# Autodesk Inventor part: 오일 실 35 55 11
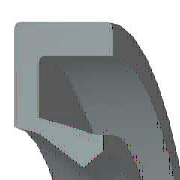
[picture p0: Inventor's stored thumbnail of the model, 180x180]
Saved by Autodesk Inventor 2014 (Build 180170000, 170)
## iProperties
IsCustomPart: 1
Created: 2012-02
Part Number: 오일 실 35 55 11
Material: 고무
Description: 오일 실 - 비스프링, 조립 GA
Document SubType Name: Modeling
Standard: JIS B 2402
Designer: mdu-01
Standards Organization: JIS
Language: ko-KR
Size Designation: 35 55 11 A
Categories: <MemberInstance><Categories><Category DisplayName="샤프트 부품" InternalName="7f7aeb1f-a693-4053-b835-cee3144e0d98" Mnemonic="SHFT"><Category DisplayName="실링" Intern
Density: 0.93 g/cm^3
Appearance: Rubber-Black
Mass: 8.95413 g
Surface Area: 69.7587 cm^2
Volume: 9.6281 cm^3
Author: mdu-01
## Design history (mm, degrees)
body "Solid1"
revolve "회전1" stored, may be unused: angle "d27" = 360 deg
fillet "모깎기1" dims "d28" = 0.55 (= 0.05 x b)
sketch "스케치2"
  geometry: L1 (20.786, -8.25)-(21.786, -11); L2 (19.452, -7.563)-(20.786, -8.25); L3 (17.5, -3.025)-(19.452, -7.563); L4 (19.038, -1.65)-(17.5, -3.025); L5 (23.5, -9.625)-(19.038, -1.65); L6 (23.5, -0.55)-(23.5, -9.625); L7 (25.5, -0.55)-(23.5, -0.55); L8 (25.5, 0)-(25.5, -0.55); L9 (27.5, 0)-(25.5, 0); L10 (27.5, -11)-(27.5, 0); L11 (21.786, -11)-(27.5, -11); L12 (0, -9.6)-(0, 1.6) reference; L13 (28, 0)-(14, 0) reference
  constraints: 22 end point, 3 horizontal, 3 vertical
  dimensions: "d2" = 11 distance of L10.start L9.start (= b); "d4" = 2 distance of L9.start L8.start (= 0.1 x dd - 0.1 x Diam); "d6" = 0.55 distance of L8.start L7.start (= 0.05 x b); "d8" = 1.53846 horizontal distance of L4.start L3.start (= 0.0769231 x dd - 0.0769231 x Diam); "d10" = 1.375 vertical distance of L5.start L10.start (= 0.125 x b); "d12" = 2 distance of L7.start L6.start (= 0.1 x dd - 0.1 x Diam); "d14" = 1.1 vertical distance of L4.start L6.start (= 0.1 x b); "d16" = 5.71429 distance of L1.end L10.start (= 0.285714 x dd - 0.285714 x Diam); "d18" = 1 horizontal distance of L1.start L1.end (= 0.05 x dd - 0.05 x Diam); "d20" = 1.375 vertical distance of L4.start L3.start (= 0.125 x b); "d22" = 2.75 vertical distance of L1.start L1.end (= 0.25 x b); "d24" = 1.33333 horizontal distance of L2.start L1.start (= 0.0666667 x dd - 0.0666667 x Diam); "d26" = 0.6875 vertical distance of L2.start L1.start (= 0.0625 x b); "d29" = 0 distance between parallel lines of L13 L9; "d30" = 17.5 distance from line of L3.start L12 (= 0.5 x Diam); "d31" = 27.5 distance between parallel lines of L12 L10 (= 0.5 x dd)
other parameters: "dd" = 55 [user parameter; used in 7 equation terms], "Diam" = 35 [user parameter; used in 7 equation terms], "b" = 11 [user parameter; used in 8 equation terms], "d1" = 8 (derived), "d3" = 2 (derived), "d5" = 0.4 (derived), "d7" = 1.53846 (derived), "d9" = 1 (derived), "d11" = 2 (derived), "d13" = 0.8 (derived), "d15" = 5.71429 (derived), "d17" = 1 (derived), "d19" = 1 (derived), "d21" = 2 (derived), "d23" = 1.33333 (derived), "d25" = 0.5 (derived), "d32" = 0
